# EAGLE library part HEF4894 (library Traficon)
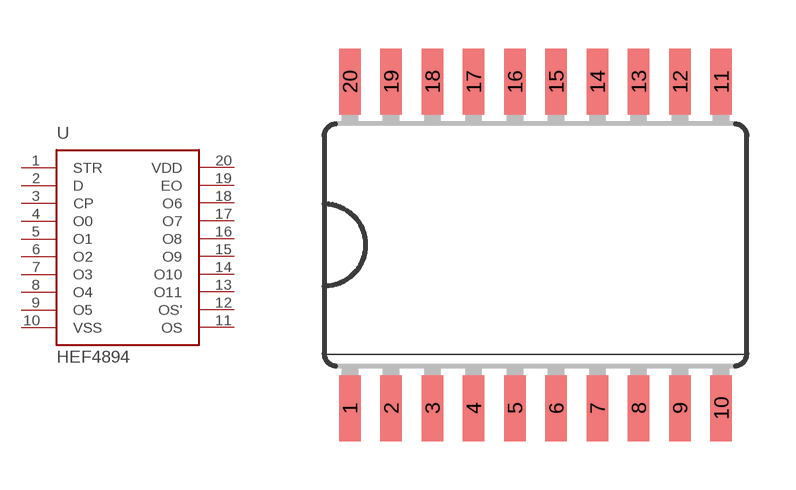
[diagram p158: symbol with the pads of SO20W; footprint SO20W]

Designator prefix U

## HEF4894  [SO20W]
1  STR  in
2  D  in
3  CP  in
4  O0  out
5  O1  out
6  O2  out
7  O3  out
8  O4  out
9  O5  out
10  VSS  pwr
11  OS  out
12  OS'  out
13  O11  out
14  O10  out
15  O9  out
16  O8  out
17  O7  out
18  O6  out
19  EO  in
20  VDD  pwr

## Footprint SO20W (pad centres in mm)
Wide Small Outline package 300 mil
smd 0.66 x 2.032: 1 -5.715,-5.029; 2 -4.445,-5.029; 3 -3.175,-5.029; 4 -1.905,-5.029; 5 -0.635,-5.029; 6 0.635,-5.029; 7 1.905,-5.029; 8 3.175,-5.029; 9 4.445,-5.029; 10 5.715,-5.029; 11 5.715,5.029; 12 4.445,5.029; 13 3.175,5.029; 14 1.905,5.029; 15 0.635,5.029; 16 -0.635,5.029; 17 -1.905,5.029; 18 -3.175,5.029; 19 -4.445,5.029; 20 -5.715,5.029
